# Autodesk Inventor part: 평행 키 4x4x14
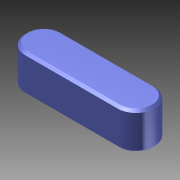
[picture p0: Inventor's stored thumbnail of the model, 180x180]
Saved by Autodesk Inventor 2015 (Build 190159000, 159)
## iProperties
Created: 2026-04
Part Number: 평행 키 4x4x14
Material: 일반
Document SubType Name: Modeling
Designer: User
Density: 1 g/cm^3
Appearance: 기본값
Author: User
Author: jhkim
Description: 키 및 해당 키홈
Creation Date: 2026-03-26
Sending System: Autodesk Inventor 2026
Preprocessor: ST-DEVELOPER v20.1
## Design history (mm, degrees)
node "평행 키 4x4x141"
body "Solid1"
node "기준1"
